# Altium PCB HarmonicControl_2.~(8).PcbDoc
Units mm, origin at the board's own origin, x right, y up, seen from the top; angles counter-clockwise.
Board outline 76.86 x 36.04 mm, 2 copper layers (Top Layer, Bottom Layer); 18 components, 24 nets, 82 pads, 11 vias.
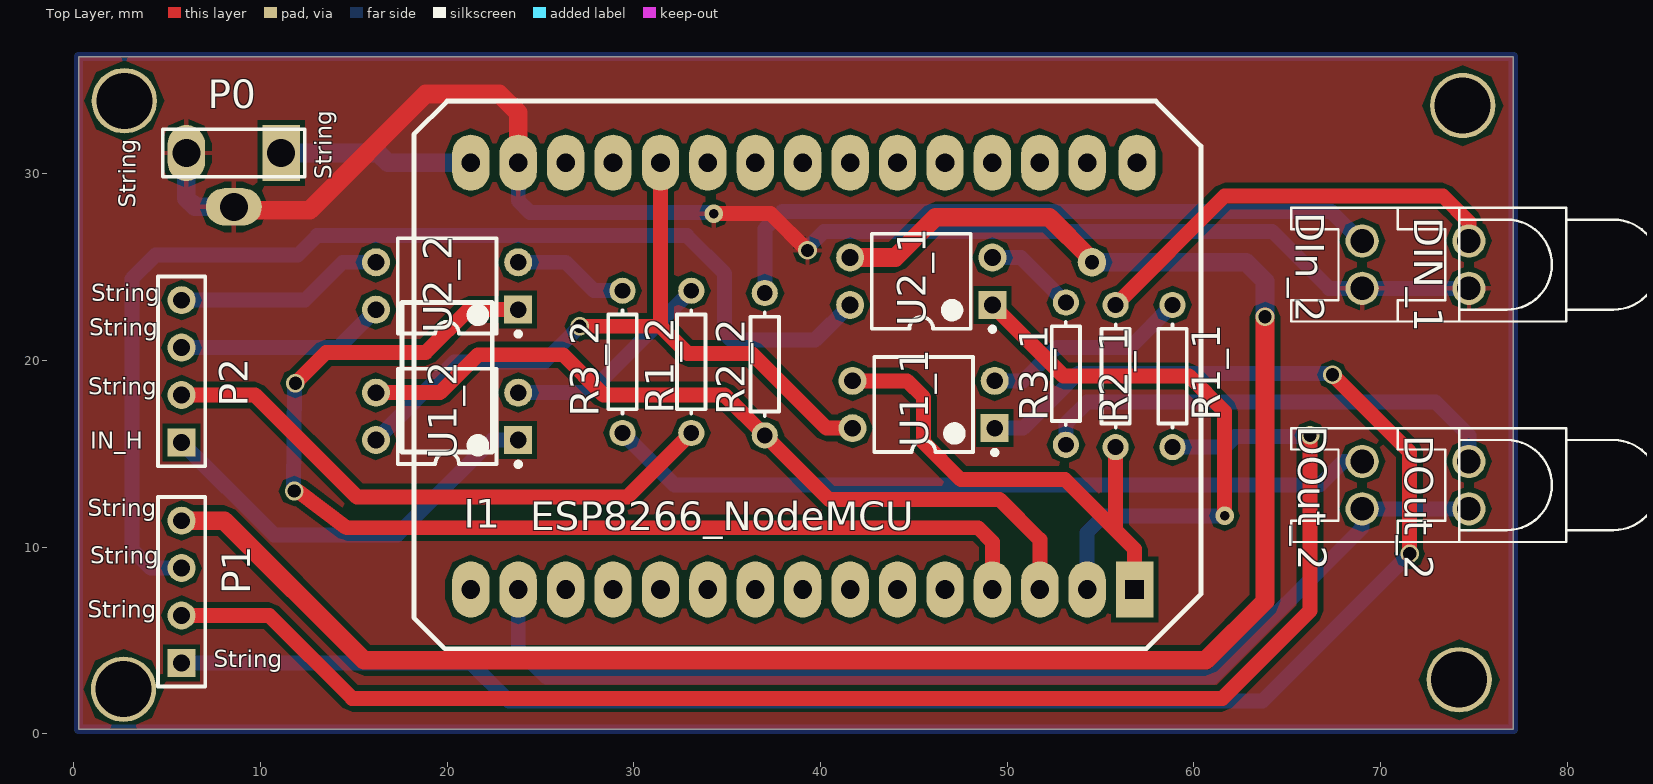
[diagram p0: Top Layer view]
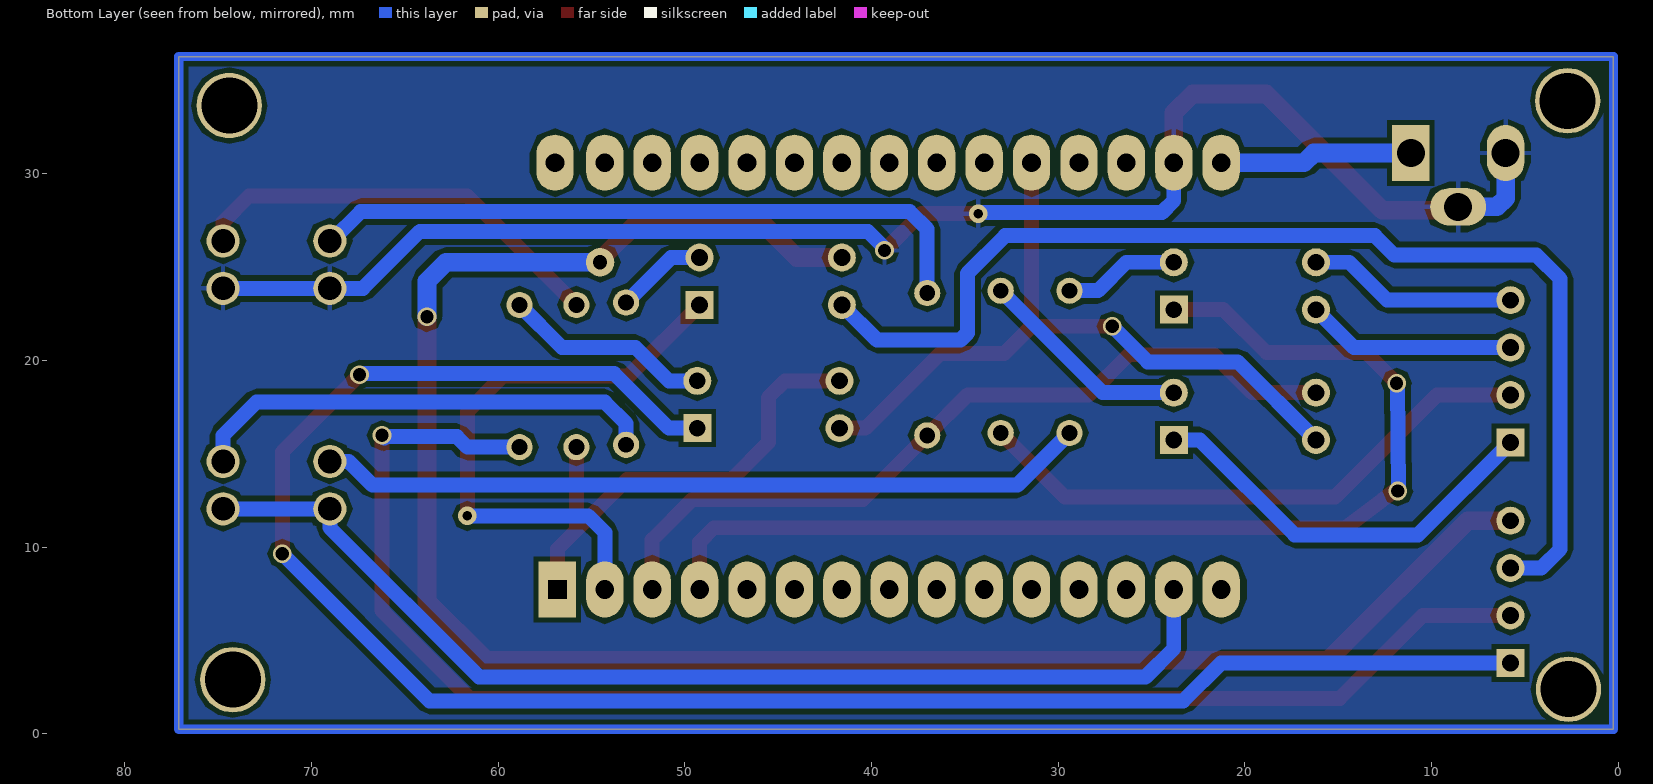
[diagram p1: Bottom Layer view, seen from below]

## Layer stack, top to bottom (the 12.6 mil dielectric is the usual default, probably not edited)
Top Solder: solder mask 0.0102, Solder Resist, Dk 3.5
Top Layer: signal copper 0.0356
Dielectric 1: dielectric 0.32, FR-4, Dk 4.8
Bottom Layer: signal copper 0.0356
Bottom Solder: solder mask 0.0102, Solder Resist, Dk 3.5

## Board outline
0.25,0.25 77.109,0.25 77.109,36.287 0.25,36.287

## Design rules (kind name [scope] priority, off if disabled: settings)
Clearance [All] p1: gap=0.254 ignorepadtopadclearanceinfootprint=FALSE except(0: Arc-Hole Track-Hole SMDPad-Hole THPad-Hole Via-Hole Fill-Hole Poly-Hole Region-Hole Text-Hole)
PolygonConnect [All] p1: connectstyle=Relief reliefconductorwidth=0.254 reliefentries=4 polygonreliefangle="90 Angle" airgapwidth=0.254
RoutingVias [All] p1: holewidth=0.711 width=1.27 viastyle="Through Hole" minholewidth=0.711 minwidth=1.27 maxholewidth=0.711 maxwidth=1.27
SolderMaskExpansion [All] p1: expansion=0.102
Width [All] p1: maxlimit=1 minlimit=0.5 preferedwidth=0.8
30 further rules are at their usual default settings.

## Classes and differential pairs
component class HarmonicControl: DIN_1 DIn_2 DOut_2 I1 P0 P1 P2 R1_1 R1_2 R2_1 R2_2 R3_1 R3_2 U1_1 U1_2 U2_1 U2_2

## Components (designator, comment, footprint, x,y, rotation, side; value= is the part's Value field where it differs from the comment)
DIN_1 "LED0" LED-0 74.734,25.137 r90 top (schematic designator D1_1)
DIn_2 "LED0" LED-0 69.019,25.137 r90 top (schematic designator D1_2)
DOut_2 "LED0" LED-0 69.019,13.326 r90 top (schematic designator D2_2)
DOut_2 "LED0" LED-0 74.734,13.326 r90 top (schematic designator D2_1)
I1 "ESP8266" ESP8266_Node_MCU_V3 21.267,30.598 r270 top
P0 "Jack3.5mm" HDR1X3 11.107,31.113 r180 top
P1 "Cable" HDR1X4 5.773,3.801 r90 top
P2 "Cable" HDR1X4 5.773,15.612 r90 top
R1_1 "Res1" AXIAL-0.3 58.859,19.168 r90 top value=1K
R1_2 "Res1" AXIAL-0.3 33.078,19.93 r90 top value=1K
R2_1 "Res1" AXIAL-0.3 55.811,19.168 r90 top value=1K
R2_2 "Res1" AXIAL-0.3 37.015,19.803 r90 top value=1K
R3_1 "Res1" AXIAL-0.3 53.144,19.295 r90 top value=1K
R3_2 "Res1" AXIAL-0.3 29.395,19.93 r90 top value=1K
U1_1 "InputSignal" DIP-4 45.524,17.644 r180 top
U1_2 "InputSignal" DIP-4 19.997,17.009 r180 top
U2_1 "Output_Control" DIP-4 45.397,24.248 r180 top
U2_2 "Output_Control" DIP-4 19.997,23.994 r180 top

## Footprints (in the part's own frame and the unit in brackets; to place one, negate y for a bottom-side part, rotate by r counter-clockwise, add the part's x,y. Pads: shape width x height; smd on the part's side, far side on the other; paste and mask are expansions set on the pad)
AXIAL-0.3 [mm] "Axial Device, Thru-Hole; 2 Leads; 0.3 in Pin Spacing"
  round 1.4 hole 0.85: 1(-3.81,0) 2(3.81,0)
  silkscreen extent -2.77,-0.76 2.77,0.76
DIP-4 [mm] "DIP; 4 Leads; Row Spacing 7.62 mm; Pitch 2.54 mm"
  rect 1.5x1.5 hole 0.9: 1(-3.81,1.27)
  round 1.5 hole 0.9: 2(-3.81,-1.27) 3(3.81,-1.27) 4(3.81,1.27)
  silkscreen extent -3.94,-2.55 2.65,2.69, body extent -3.15,-2.5 3.15,2.5, height 5.6
ESP8266_Node_MCU_V3 [mm]
  rect 3x2 hole 1 square paste+0 mask+0.102: 1(22.86,35.56)
  oval 3x2 hole 1 paste+0 mask+0.102: 2(22.86,33.02) 3(22.86,30.48) 4(22.86,27.94) 5(22.86,25.4) 6(22.86,22.86) 7(22.86,20.32) 8(22.86,17.78) 9(22.86,15.24) 10(22.86,12.7) 11(22.86,10.16) 12(22.86,7.62) 13(22.86,5.08) 14(22.86,2.54) 15(22.86,0) 16(0,0) 17(0,2.54) 18(0,5.08) 19(0,7.62) 20(0,10.16) 21(0,12.7) 22(0,15.24) 23(0,17.78) 24(0,20.32) 25(0,22.86) 26(0,25.4) 27(0,27.94) 28(0,30.48) 29(0,33.02) 30(0,35.687)
  silkscreen extent -3.3,-3.68 26.04,39.12
HDR1X3 [mm] "Connector; Header; 3 Position"
  rect 2x3 hole 1.5: 1(0,0)
  oval 3x2 hole 1.5: 2(2.54,2.881)
  oval 2x3 hole 1.5: 3(5.08,0)
  silkscreen extent -1.27,-1.27 6.35,1.27
HDR1X4 [mm] "Connector; Header; 4 Position"
  rect 1.5x1.5 hole 0.9: 1(0,0)
  round 1.5 hole 0.9: 2(2.54,0) 3(5.08,0) 4(7.62,0)
  silkscreen extent -1.27,-1.27 8.89,1.27
LED-0 [mil] "LED; 2 Leads"
  round 70 hole 50: 1(50,0) 2(-50,0)
  silkscreen extent -120,-400 120,150

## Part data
DIN_1 DIn_2 DOut_2 DOut_2: "Typical INFRARED GaAs LED"
I1: library part ESP8266_Node_MCU_V3
P0: library part "Header 3", "Header, 3-Pin"
P1 P2: library part "Header 4", "Header, 4-Pin"
R1_1 R1_2 R2_1 R2_2 R3_1 R3_2: "Resistor"
U1_1 U1_2 U2_1 U2_2: library part Optoisolator1, "4-Pin Phototransistor Optocoupler"

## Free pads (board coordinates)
  round 1.524 hole 0.762: 2(54.541,25.264)
  round 3.5 hole 3: 12(2.705,33.913) 15(74.405,33.659) 16(2.664,2.392) 17(74.214,2.901)

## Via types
v1: diameter 1, hole 0.711, Top Layer to Bottom Layer, 9 vias
v2: diameter 1, hole 0.5, Top Layer to Bottom Layer, 2 vias

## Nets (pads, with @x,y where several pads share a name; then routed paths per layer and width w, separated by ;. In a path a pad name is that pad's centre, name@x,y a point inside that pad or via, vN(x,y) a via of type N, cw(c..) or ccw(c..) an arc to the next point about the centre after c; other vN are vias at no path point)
GND: DIN_1.2 DIn_2.2 I1.17 P0.2 P0.3 | length 80.6
  Top Layer w0.8: v2(34.284,27.867) 37.332,27.867 v1(39.301,25.899)
  Top Layer w1: P0.2@9.623,28.058 12.631,28.058 18.854,34.281 22.791,34.281 23.807,33.265 I1.17
  Bottom Layer w0.8: I1.17 23.807,28.566 24.442,27.931 v2@34.094,27.931 ; v1@39.237,25.962 40.197,26.922 64.193,26.922 67.248,23.867 DIn_2.2 DIN_1.2
  Bottom Layer w1: P0.3 6.027,28.7 6.495,28.232 P0.2
NetD1_1_1: DIN_1.1 R2_1.2 | length 22.9
  Top Layer w0.8: R2_1.2 61.653,28.82 73.337,28.82 74.734,27.423 DIN_1.1
NetD1_2_1: DIn_2.1 R2_2.2 | length 36.5
  Bottom Layer w0.8: R2_2.2 37.015,27.042 37.949,27.976 67.368,27.976 68.937,26.407 DIn_2.1
NetD2_1_1: DOut_2.1@74.734,14.596 R3_1.1 | length 25.3
  Bottom Layer w0.8: R3_1.1 53.144,16.628 54.287,17.771 72.956,17.771 74.734,15.993 DOut_2.1@74.734,14.596
NetD2_1_2: DOut_2.2 I1.14 | length 59.1
  Bottom Layer w0.8: I1.14 23.807,4.563 25.324,3.046 61.018,3.046 69.019,11.047 69.019,12.056 DOut_2.2@74.734,12.056
NetD2_2_1: DOut_2.1@69.019,14.596 R3_2.1 | length 41.3
  Bottom Layer w0.8: R3_2.1 32.182,13.333 66.74,13.333 68.003,14.596 DOut_2.1@69.019,14.596
NetI1_1: I1.1 R2_1.1 U1_1.3 | length 26.9
  Top Layer w0.8: U1_1.3 44.635,18.914 45.524,18.025 45.524,15.612 47.518,13.618 53.106,13.618 55.811,10.913 ; R2_1.1 55.811,10.913 ; I1.1 56.827,9.897 55.811,10.913
NetI1_2: I1.2 U2_1.1 | length 31.2
  Top Layer w0.8: U2_1.1 53.017,19.168 59.748,19.168 61.653,17.263 v2(61.653,11.682)
  Bottom Layer w0.8: I1.2 54.287,10.793 55.176,11.682 v2(61.653,11.682)
NetI1_3: I1.3 R2_2.1 U1_2.3 | length 43.2
  Top Layer w0.8: U1_2.3 19.616,18.279 21.648,20.311 26.22,20.311 28.379,18.152 34.856,18.152 R2_2.1 40.444,12.564 49.588,12.564 51.747,10.405 I1.3
NetI1_4: I1.4 U2_2.1 | length 60.2
  Top Layer w0.8: v1@11.783,12.978 11.809,12.982 11.996,13.008 14.621,11.04 48.445,11.04 49.207,10.278 I1.4 ; v1(11.869,18.787) 13.52,20.438 18.854,20.438 21.14,22.724 U2_2.1
  Bottom Layer w0.8: v1@11.746,13.009 11.758,13.02 v1@11.817,18.715
  other v1: 11.805,13.008
NetI1_16: I1.16 P0.1 | length 10.4
  Bottom Layer w1: P0.1 16.314,31.113 16.829,30.598 I1.16
NetI1_20: I1.20 U1_1.4 U1_2.4 | length 39.1
  Top Layer w0.8: v1(27.109,21.835) 31.427,21.835 ; I1.20 31.427,21.835 ; U1_1.4 40.317,16.374 36.304,20.387 32.875,20.387 31.427,21.835
  Bottom Layer w0.8: U1_2.4 20.378,19.93 25.204,19.93 v1(27.109,21.835)
NetP1_1: P1.1 U1_1.1 | length 100.2
  Top Layer w0.8: v1@67.622,19.041 71.559,15.104 v1(71.559,9.643)
  Bottom Layer w0.8: P1.1 21.267,3.801 23.299,1.769 63.685,1.769 v1(71.559,9.643) ; U1_1.1 50.858,16.374 53.779,19.295 v1@67.368,19.295
  other v1: 67.431,19.231
NetP1_2: P1.2 R1_1.1 | length 81.1
  Top Layer w0.8: P1.2 10.472,6.341 14.91,1.903 61.533,1.903 66.225,6.595 v1@66.225,15.739
  Bottom Layer w0.8: R1_1.1 61.653,15.358 62.215,15.92 v1@66.033,15.92 ; v1@66.098,15.858 v1@66.033,15.92 ; v1(66.225,15.993) 66.152,15.92 v1@66.033,15.92
NetP1_3: P1.3 U2_1.4 | length 62
  Bottom Layer w0.8: P1.3 4.122,8.881 3.106,9.897 3.106,24.375 4.376,25.645 11.996,25.645 13.037,26.686 32.84,26.686 34.856,24.67 34.856,21.479 35.237,21.098 39.707,21.098 U2_1.4
NetP1_4: P1.4 pad.2 U2_1.3 | length 103.9
  Top Layer w1: P1.4 8.059,11.421 15.545,3.935 60.644,3.935 63.812,7.103 v1(63.812,22.343) ; U2_1.3 44,25.518 46.159,27.677 52.255,27.677 pad.2@54.414,25.518
  Bottom Layer w1: v1(54.541,25.264) 62.796,25.264 63.812,24.248 v1(63.812,22.343) ; v1@63.809,22.34 v1@63.809,22.343
NetP2_1: P2.1 U1_2.1 | length 22.2
  Bottom Layer w0.8: P2.1 10.726,10.659 17.33,10.659 22.41,15.739 U1_2.1
NetP2_2: P2.2 R1_2.1 | length 31
  Top Layer w0.8: P2.2 9.71,18.152 15.171,12.691 29.649,12.691 R1_2.1
NetP2_3: P2.3 U2_2.4 | length 11.3
  Bottom Layer w0.8: P2.3 14.155,20.692 U2_2.4
NetP2_4: P2.4 U2_2.3 | length 11.3
  Bottom Layer w0.8: P2.4 12.377,23.232 14.409,25.264 U2_2.3
NetR1_1_2: R1_1.2 U1_1.2 | length 11.2
  Bottom Layer w0.8: U1_1.2 50.858,18.914 52.636,20.692 56.573,20.692 R1_1.2
NetR1_2_2: R1_2.2 U1_2.2 | length 11.5
  Bottom Layer w0.8: U1_2.2 27.617,18.279 R1_2.2
NetR3_1_2: R3_1.2 U2_1.2 | length 4.9
  Bottom Layer w0.8: U2_1.2 50.731,25.518 R3_1.2
NetR3_2_2: R3_2.2 U2_2.2 | length 6.2
  Bottom Layer w0.8: U2_2.2 26.347,25.264 27.871,23.74 R3_2.2
pads on no net: I1.5 I1.6 I1.7 I1.8 I1.9 I1.10 I1.11 I1.12 I1.13 I1.15 I1.18 I1.19 I1.21 I1.22 I1.23 I1.24 I1.25 I1.26 I1.27 I1.28 I1.29 I1.30
copper on no net: | length 225.8
  Bottom Layer w0.5: 0.25,0.25 77.109,0.25 77.109,36.287 0.25,36.287 0.25,0.25

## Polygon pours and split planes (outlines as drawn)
GND on Bottom Layer "GND_L02_P031" (solid, remove dead copper, pour order 31): 0.25,36.287 77.109,36.287 77.109,0.25 0.25,0.25
GND on Bottom Layer "GND_L02_P029" (solid, remove dead copper, pour order 29): 0.058,36.444
GND on Top Layer "GND_L01_P027" (solid, remove dead copper, pour order 27): 0.25,36.287 0.25,0.25 77.109,0.25 77.109,36.287

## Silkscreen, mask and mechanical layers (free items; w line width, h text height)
Top Overlay:
  text "String" at 14.113,29.703 h1.52 r90
  text "String" at 3.618,28.171 h1.52 r90
  text "String" at 0.946,22.892 h1.52
  text "String" at 0.816,21.034 h1.52
  text "String" at 0.783,17.873 h1.52
  text "IN_H" at 0.866,14.992 h1.52
  text "String" at 0.75,11.355 h1.52
  text "String" at 0.881,8.813 h1.52
  text "String" at 0.75,5.912 h1.52
  text "String" at 7.497,3.272 h1.52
